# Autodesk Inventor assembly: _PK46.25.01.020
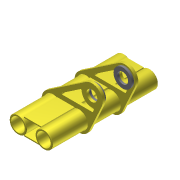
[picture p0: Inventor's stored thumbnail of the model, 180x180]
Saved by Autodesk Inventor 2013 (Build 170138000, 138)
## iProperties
Created: 2012-04
Part Number: _PK46.25.01.020
Document SubType Name: Assembly
Designer: Dale
Author: Dale
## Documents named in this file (7)
- C:\Product Design Suite 2013 Test Drive\Inventor Optimization\Workspace\Assy, Chassis, Front\_PK46.25.01.020.iam
- C:\Product Design Suite 2013 Test Drive\Inventor Optimization\Workspace\Assy, Chassis, Front\PK46.25.01.005.ipt
- C:\Product Design Suite 2013 Test Drive\Inventor Optimization\Workspace\Assy, Chassis, Front\PK46.25.01.006.ipt
- C:\Product Design Suite 2013 Test Drive\Inventor Optimization\Workspace\Assy, Chassis, Front\PK46.25.01.007.ipt
- C:\Product Design Suite 2013 Test Drive\Inventor Optimization\Workspace\Assy, Chassis, Front\PK46.25.01.009.ipt
- C:\Product Design Suite 2013 Test Drive\Inventor Optimization\Workspace\Assy, Chassis, Front\PK46.25.01.009-01.ipt
- C:\Product Design Suite 2013 Test Drive\Inventor Optimization\Workspace\Assy, Chassis, Front\PK46.25.01.016.ipt
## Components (12 placed, 6 different names)
1. PK46.25.01.005:1
2. PK46.25.01.005:2
3. PK46.25.01.006:1
4. PK46.25.01.006:2
5. PK46.25.01.007:1
6. PK46.25.01.007:2
7. PK46.25.01.009:1
8. PK46.25.01.009-01:1
9. PK46.25.01.009-01:2
10. PK46.25.01.009-01:3
11. PK46.25.01.009-01:4
12. PK46.25.01.016:1
## Named parameters: d5_d12 = 0, d6_d15 = 0, d7_d18 = 0
